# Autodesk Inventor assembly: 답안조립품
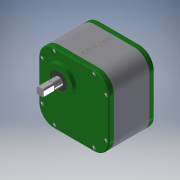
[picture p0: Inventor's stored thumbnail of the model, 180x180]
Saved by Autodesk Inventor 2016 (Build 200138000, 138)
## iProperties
Created: 2017-11
Part Number: 답안조립품
Material: 일반
Document SubType Name: Assembly
Designer: 605-04
Mass: 3103.18 g
Surface Area: 2353.72 cm^2
Volume: 855.506 cm^3
Density: 3.62731 g/cm^3
Author: 605-04
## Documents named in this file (11)
- C:\Users\605-04\Desktop\371107V1018\답안조립품.iam
- C:\Users\605-04\Desktop\371107V1018\본체.ipt
- C:\Users\605-04\Desktop\371107V1018\뒤커버.ipt
- C:\Users\605-04\Desktop\371107V1018\베어링 608.ipt
- C:\Users\605-04\Desktop\371107V1018\베어링 6003.ipt
- C:\Users\605-04\Desktop\371107V1018\오일실 8 22 7.ipt
- C:\Users\605-04\Desktop\371107V1018\볼트 M4.ipt
- C:\Users\605-04\Desktop\371107V1018\메인축.ipt
- C:\Users\605-04\Desktop\371107V1018\서브축.ipt
- C:\Users\605-04\Desktop\371107V1018\앞커버.ipt
- C:\Users\605-04\Desktop\371107V1018\오일실 17 32 8.ipt
